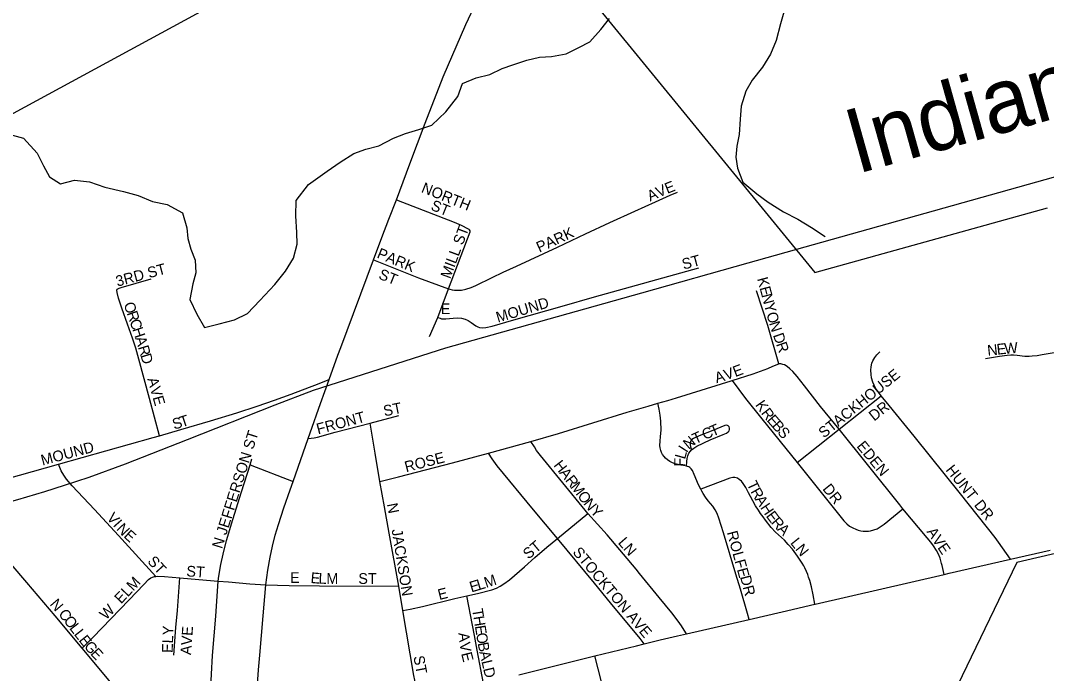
# Model space of a CAD drawing. Extents: x 1442749 to 1756758, y 235267 to 677782.
# Drawn here: x 1646641 to 1651408, y 544298 to 547333 of the extents above; entities that cross this region are included whole.
import ezdxf

# ---------------------------------------------------------------- set-up
doc = ezdxf.new("R2010")
doc.units = 0
for name, color, linetype in [('GM_X_City_Street', 7, 'Continuous'), ('GM_X_City_Street_Text', 7, 'Continuous'), ('GM_X_Corporation', 7, 'Continuous'), ('GM_X_Minor_River', 7, 'Continuous'), ('GM_X_Rail_Line', 7, 'Continuous'), ('GM_X_Rail_Line_Text', 7, 'Continuous'), ('GM_X_State_Route', 7, 'Continuous'), ('GM_X_US_Route', 7, 'Continuous')]:
    doc.layers.add(name, color=color, linetype=linetype)

msp = doc.modelspace()

# ---------------------------------------------------------------- linework, layer by layer
at = {"layer": 'GM_X_City_Street'}
for points in [[(1648629.7, 546086.1), (1648635.4, 546084.4), (1648646.7, 546082.1), (1648658, 546080.3), (1648674.3, 546079.3), (1648690.6, 546080.5), (1648709.9, 546084.4), (1648735, 546092.1), (1648756.2, 546100.9), (1648832.5, 546138.9), (1648882.9, 546162.7), (1648945.1, 546192), (1649135.5, 546280.2), (1649266.1, 546341.5), (1649379.2, 546393.9), (1649495.8, 546446.3), (1649591, 546490.4), (1649659.7, 546521.4), (1649693.3, 546534.6)], [(1648387.4, 546500.2), (1648656.3, 546396.2), (1648689.2, 546381.5), (1648721.2, 546365), (1648724, 546363.3), (1648727.5, 546359.9)], [(1648629.7, 546086.1), (1648729.7, 546351), (1648729.7, 546355.9), (1648727.5, 546359.9)], [(1648280.6, 546220.6), (1648490.8, 546137.6), (1648629.7, 546086.1)], [(1648580.4, 545953.1), (1648591.2, 545949.2), (1648597.5, 545947), (1648605.5, 545946.1), (1648618, 545947), (1648651.5, 545950.4), (1648671.2, 545951), (1648690.8, 545949.4), (1648706.7, 545945.4), (1648721.4, 545938.4), (1648735.1, 545929.3), (1648756.6, 545913.9), (1648765.2, 545909.3), (1648774.3, 545906), (1648787.2, 545904.2), (1648803.4, 545905.9), (1648832.2, 545912.9), (1648933.1, 545942), (1649157.3, 546005), (1649308.7, 546048.4), (1649792.4, 546183.4)], [(1647089.8, 546084.5), (1647100.1, 546089.4), (1647108.6, 546092.1), (1647247.7, 546132.5)], [(1647287.4, 545403.1), (1647240.7, 545576.6), (1647215.9, 545668.2), (1647190.8, 545759.7), (1647176.1, 545810.1), (1647161.8, 545856.9), (1647138.7, 545921.6), (1647112.2, 545996), (1647096.6, 546042), (1647089.8, 546069.7), (1647089, 546079.1), (1647089.8, 546084.5)], [(1648580.4, 545953.1), (1648629.7, 546086.1)], [(1650165.1, 545737.4), (1650113.2, 545915.3), (1650061.4, 546077.4)], [(1648541.5, 545864.6), (1648580.4, 545953.1)], [(1651125.6, 545761.6), (1651190.2, 545773.4), (1651225.9, 545777.9), (1651242.2, 545778.7), (1651255.5, 545778.7), (1651271.7, 545778), (1651307.5, 545773.7), (1651327.1, 545773), (1651342.1, 545774), (1651365.5, 545776.7), (1651388.9, 545780.6), (1652010, 545884.6), (1652235.6, 545927.9), (1652271, 545935.5), (1652290.3, 545939.3), (1652313.4, 545942.8), (1652329.9, 545942.9), (1652337, 545942.2)], [(1650640, 545588.9), (1650631.7, 545599.1), (1650616.5, 545620.4), (1650607.1, 545637.7), (1650600.8, 545652.8), (1650595.3, 545671.6), (1650592.9, 545687.9), (1650592.2, 545707.5), (1650593.6, 545723.8), (1650597.2, 545739.8), (1650601.9, 545752.1), (1650610.1, 545766.2), (1650620.2, 545779.1), (1650633.7, 545793.4)], [(1649947.6, 545659.3), (1650045.4, 545691.5), (1650113, 545716.4), (1650137.4, 545726.1), (1650165.1, 545737.4)], [(1650444.3, 545433.6), (1650358.5, 545539.4), (1650284.6, 545635.8), (1650249.8, 545679.3), (1650230.2, 545701.3), (1650215.9, 545714.8), (1650202.7, 545724.5), (1650190.2, 545732.4), (1650183.5, 545735.1), (1650174.5, 545737.4), (1650165.1, 545737.4)], [(1647287.4, 545403.1), (1647386.1, 545431.8), (1647524.5, 545472.7), (1647646.7, 545510.1), (1647740, 545541.3), (1647820.8, 545568.4), (1647897.8, 545596.3), (1647983.6, 545628.9), (1648008, 545638.4), (1648074.5, 545664.5)], [(1649603.1, 545554), (1649648.3, 545567.1), (1649689.1, 545579.3), (1649942.7, 545657.7), (1649947.6, 545659.3)], [(1649947.6, 545659.3), (1650009.7, 545576.8), (1650085.6, 545482.3), (1650249, 545278.8)], [(1650444.3, 545433.6), (1650640, 545588.9)], [(1651240.6, 544829.5), (1651185.5, 544908.9), (1651169.9, 544929.9), (1651008.8, 545132.6), (1650793, 545400.7), (1650677.4, 545543.3), (1650640, 545588.9)], [(1649012.3, 545377.2), (1649140.5, 545413.3), (1649459.5, 545512.3), (1649557, 545540.6), (1649603.1, 545554)], [(1649736.1, 545261.4), (1649720.9, 545264.3), (1649709.3, 545266.6), (1649696.8, 545269.3), (1649683.4, 545272.4), (1649670.7, 545277.1), (1649658, 545284.1), (1649646.8, 545291.7), (1649638.3, 545298.4), (1649631.1, 545306), (1649624, 545315.3), (1649618.6, 545325.6), (1649615.9, 545334.6), (1649613.7, 545347.1), (1649612.3, 545358.3), (1649613.5, 545377.4), (1649615, 545399.4), (1649617.7, 545429.6), (1649616.4, 545471.7), (1649613.3, 545499.2), (1649608.1, 545527), (1649603.1, 545554)], [(1648265.2, 545462.2), (1648398.7, 545497.1)], [(1647977.3, 545390), (1648005.6, 545393.8), (1648020.4, 545396.9), (1648103.1, 545419.8), (1648265.2, 545462.2)], [(1648311.1, 545191.1), (1648288.7, 545321.5), (1648265.2, 545462.2)], [(1649736.1, 545261.4), (1649737.8, 545284), (1649738.9, 545297.1), (1649741.7, 545310), (1649746.6, 545322.2), (1649751.9, 545330.5), (1649759, 545338), (1649769.5, 545345.8), (1649782.8, 545354.4), (1649845.4, 545383.6), (1649906.3, 545408.3), (1649920.9, 545415.7), (1649929.3, 545421.1), (1649933.8, 545425.8), (1649936.1, 545431.8), (1649936, 545438.4), (1649933.5, 545444.4), (1649928.9, 545449), (1649926, 545450.5), (1649919.7, 545451.8), (1649913.3, 545450.8), (1649858.5, 545428.2), (1649794.4, 545402.5), (1649767.7, 545389.8), (1649760.1, 545385.1), (1649755.7, 545379.1), (1649753, 545370.8), (1649752.5, 545362.3), (1649754.8, 545351.6), (1649759, 545338)], [(1650249, 545278.8), (1650444.3, 545433.6)], [(1650741.3, 545064), (1650726.5, 545081.8), (1650444.3, 545433.6)], [(1646817.2, 545271.3), (1647257, 545394.3), (1647287.4, 545403.1)], [(1648815.8, 545321.9), (1649012.3, 545377.2)], [(1649277.4, 545042.2), (1649264.2, 545057), (1649056.6, 545310.7), (1649038.8, 545334.1), (1649028.5, 545350.9), (1649012.3, 545377.2)], [(1647707.5, 545267.8), (1647716.2, 545295.9)], [(1648311.1, 545191.1), (1648397, 545212.3), (1648647.6, 545277.6), (1648815.8, 545321.9)], [(1649135.4, 544925.1), (1649024.6, 545058.5), (1648856.2, 545263.7), (1648833, 545295.5), (1648815.8, 545321.9)], [(1646322, 545131.4), (1646817.2, 545271.3)], [(1647270.1, 544749.5), (1647095.5, 544939), (1646984.7, 545060.2), (1646881, 545170.5), (1646855.3, 545200.8), (1646841.5, 545219.8), (1646830.4, 545240.9), (1646817.2, 545271.3)], [(1647560, 544727.6), (1647562.6, 544750.3), (1647572, 544805.1), (1647582.3, 544853.2), (1647598.5, 544916.8), (1647627.7, 545014.2), (1647668.5, 545142.4), (1647707.5, 545267.8)], [(1647707.5, 545267.8), (1647908.1, 545190.6)], [(1649802.2, 545155.3), (1649791.7, 545175.8), (1649771.1, 545223.8), (1649762.9, 545241.7), (1649757.6, 545250.1), (1649751.8, 545255.5), (1649746, 545258.6), (1649740.1, 545260.6), (1649736.1, 545261.4)], [(1650249, 545278.8), (1650467.2, 545007.2), (1650480.9, 544993.1), (1650493.6, 544982.9), (1650507.7, 544974.6), (1650522.8, 544968.3), (1650533.4, 544964.6), (1650545.5, 544961.9), (1650557.1, 544960.1), (1650568.7, 544959.2), (1650581.2, 544959.6), (1650590.4, 544960.9), (1650606.2, 544965.3), (1650621.4, 544971.3), (1650635.7, 544979.2), (1650654.4, 544992.6), (1650741.3, 545064)], [(1648398.1, 544703.7), (1648354.1, 544950.3), (1648332.5, 545073), (1648311.1, 545191.1)], [(1650332.5, 544620.3), (1650323.6, 544663.1), (1650315.7, 544701.3), (1650308.3, 544730.4), (1650303.2, 544745.4), (1650298.8, 544758.3), (1650292.9, 544772.8), (1650285.2, 544789.4), (1650280.4, 544798.7), (1650272.3, 544811), (1650263.8, 544825.1), (1650250.8, 544844.1), (1650227.5, 544875.8), (1650208.5, 544898.5), (1650190.3, 544917.3), (1650149.6, 544955.6), (1650129.6, 544977.3), (1650102.6, 545010.4), (1650091.1, 545026.2), (1650079.4, 545042.2), (1650069.8, 545057.2), (1650056.4, 545078.1), (1650043.6, 545101.1), (1650032.3, 545121.1), (1650023.2, 545138.5), (1650011, 545161.9), (1649998.9, 545181.5), (1649990.7, 545191.7), (1649981, 545200.5), (1649972.6, 545205.6), (1649966.5, 545207.8), (1649960.1, 545208.9), (1649950.3, 545208.5), (1649937.5, 545205.6), (1649802.2, 545155.3)], [(1650027.1, 544549.4), (1650019, 544577.5), (1649986.4, 544690.9), (1649965.2, 544759.9), (1649907.9, 544951.7), (1649886.4, 545020.6), (1649878, 545042), (1649868.7, 545059.2), (1649857.5, 545075.4), (1649836.4, 545100.5), (1649823.3, 545118.3), (1649812.9, 545134.3), (1649807.1, 545145.5), (1649802.2, 545155.3)], [(1650932.8, 544759), (1650923.4, 544799.6), (1650921, 544809.1), (1650913.8, 544834.3), (1650906.5, 544852.6), (1650897.1, 544869.8), (1650882.6, 544891.6), (1650870.3, 544908.7), (1650854.5, 544928), (1650741.3, 545064)], [(1649135.4, 544925.1), (1649277.4, 545042.2)], [(1649735.5, 544483), (1649717.7, 544512.1), (1649712.5, 544520.5), (1649697.3, 544541.8), (1649666.8, 544580.4), (1649608.6, 544651.2), (1649517.1, 544762.7), (1649501, 544783.1), (1649366.7, 544942.1), (1649277.4, 545042.2)], [(1646926.7, 544416.6), (1646801.7, 544566.9), (1646670.2, 544721.8), (1646513.7, 544903.1)], [(1648715.1, 544658.8), (1648764.2, 544669.8), (1648830.8, 544687.5), (1648852.4, 544695.2), (1648870.1, 544703.9), (1648886.8, 544714.2), (1648912.7, 544734.3), (1648982.3, 544794.2), (1649031.5, 544837.7), (1649086.1, 544884.9), (1649135.4, 544925.1)], [(1649539.6, 544436.1), (1649519.9, 544460.1), (1649382.5, 544627.1), (1649307.5, 544718.2), (1649135.4, 544925.1)], [(1646926.7, 544416.6), (1646976.8, 544466.2), (1647146.1, 544640.3), (1647213.7, 544711.9), (1647236.4, 544734.9), (1647246.3, 544742.3), (1647254.3, 544746.2), (1647262.9, 544748.7), (1647270.1, 544749.5)], [(1647270.1, 544749.5), (1647279.6, 544750.6), (1647310.7, 544748.7), (1647380.6, 544742.4)], [(1647353, 544383.2), (1647363.4, 544512.7), (1647369.7, 544591.5), (1647380.6, 544742.4)], [(1647380.6, 544742.4), (1647434.6, 544738), (1647560, 544727.6)], [(1647518.4, 544129.4), (1647523.5, 544207.6), (1647532.8, 544381.2), (1647547.9, 544564.2), (1647560, 544727.6)], [(1647560, 544727.6), (1647608, 544723.7), (1647706, 544715.3), (1647780.5, 544710.2)], [(1647780.5, 544710.2), (1647889, 544707.9), (1648029.7, 544706.1), (1648398.1, 544703.7)], [(1648418, 544590.5), (1648398.1, 544703.7)], [(1648418, 544590.5), (1648452.2, 544597.4), (1648508.8, 544609.4), (1648658.5, 544646.1), (1648715.1, 544658.8)], [(1648792.1, 544251.8), (1648762.5, 544407), (1648750.3, 544474.4), (1648741.6, 544522.3), (1648715.1, 544658.8)], [(1648496.2, 544178.1), (1648488.9, 544203.2), (1648477.7, 544244.8), (1648469.2, 544289), (1648418, 544590.5)], [(1647157.7, 544139.9), (1647104, 544204.3), (1646998.8, 544330), (1646926.7, 544416.6)], [(1649446.5, 543840.7), (1649373.8, 544132.7), (1649309.1, 544379.8)]]:
    msp.add_lwpolyline(points, dxfattribs=at)
at = {"layer": 'GM_X_Corporation'}
for points in [[(1648778.3, 548061.1), (1650332.2, 546161.2), (1651413, 546463.1)], [(1652114.9, 545011.1), (1651269.8, 544813.5), (1650361.2, 542928.4), (1651124.9, 542577.6), (1650104.1, 541664), (1649520.7, 542211.3), (1648766.1, 541499), (1648482, 541930.2), (1646734.2, 541962.5), (1645443.9, 543575.4), (1644770.3, 543343.8), (1644478.4, 543615.9), (1644333.9, 543780.2), (1643956.3, 544219.1), (1643887.6, 544303.8), (1644660.8, 544533), (1644252.8, 545033.8), (1646118.2, 546637.1), (1648217.2, 547777.1)]]:
    msp.add_lwpolyline(points, dxfattribs=at)
at = {"layer": 'GM_X_Minor_River'}
for points in [[(1646587.1, 546804.7), (1646655.2, 546785.8), (1646718.6, 546716.9), (1646748, 546658.4), (1646775.5, 546606), (1646827.3, 546573.3), (1646891.8, 546590.6), (1646962.1, 546583.8), (1647032.1, 546559), (1647120.2, 546537.9), (1647188.3, 546519.1), (1647254.2, 546492.3), (1647322.4, 546477.5), (1647394.2, 546438.6), (1647413.5, 546370.2), (1647418.9, 546319.9), (1647432.3, 546269.7), (1647451.8, 546219.3), (1647455.1, 546161.1), (1647442.4, 546109.1), (1647427.5, 546037), (1647460.8, 545968.5), (1647496.2, 545905.9), (1647564.7, 545923.2), (1647635.3, 545942.4), (1647695.9, 545971.8), (1647752.9, 546031.4), (1647822.1, 546106.8), (1647873, 546168.4), (1647909.9, 546228.2), (1647926.8, 546294.2), (1647925.4, 546348.3), (1647920.3, 546424.6), (1647921.2, 546496.8), (1647978.4, 546570.4), (1648065.5, 546633.6), (1648126.3, 546675), (1648189, 546714.4), (1648245.5, 546735.8), (1648306, 546751.2), (1648374.7, 546786.5), (1648429.2, 546808), (1648491.7, 546827.3), (1648552.2, 546846.7), (1648617.2, 546908.2), (1648672.3, 546979.8), (1648695.1, 547039.7), (1648757.7, 547067), (1648822.2, 547082.4), (1648878.8, 547109.8), (1648929.2, 547127.3), (1648993.8, 547148.6), (1649052.2, 547162), (1649108.5, 547165.4), (1649176.9, 547178.7), (1649235.5, 547208.1), (1649286.1, 547233.6), (1649337, 547291.2), (1649377.8, 547342.9)], [(1650187.7, 547371.8), (1650173, 547317.9), (1650151.9, 547239.9), (1650125.1, 547176), (1650088.2, 547116.2), (1650041.2, 547056.6), (1650010.5, 547004.8), (1649989.6, 546934.8), (1649984.8, 546874.7), (1649979.9, 546802.6), (1649969.2, 546748.5), (1649964.6, 546698.4), (1649972, 546646.2), (1649997.3, 546581.7), (1650063, 546526.8), (1650114.7, 546488.2), (1650186.5, 546443.2), (1650252.4, 546410.4), (1650316.2, 546371.6), (1650380, 546328.7)]]:
    msp.add_lwpolyline(points, dxfattribs=at)
at = {"layer": 'GM_X_Rail_Line'}
for points in [[(1648002.1, 545614.9), (1648617.4, 545811.2), (1649528.4, 546067.5), (1650021.6, 546206.3), (1652489.5, 546898.6), (1654040.9, 547332.8), (1657745.4, 548373), (1661321.1, 549378.1), (1663701.4, 550047.2)], [(1647824.1, 545546.7), (1648002.1, 545614.9)], [(1622992.7, 538441.5), (1624973.8, 539013.5), (1626935.6, 539566.6), (1628793.5, 540088.9), (1634516, 541702.1), (1636441.8, 542242.9), (1638391.8, 542790.8), (1640631.9, 543421.9), (1643762.7, 544302.3), (1646454, 545058.4), (1646629.2, 545107.3), (1646753.5, 545144.7), (1646845.5, 545173.3), (1646960.4, 545211.3), (1647129.3, 545272.7), (1647416.4, 545385.5), (1647824.1, 545546.7)]]:
    msp.add_lwpolyline(points, dxfattribs=at)
at = {"layer": 'GM_X_State_Route'}
for points in [[(1648129.3, 545813.6), (1648280.6, 546220.6), (1648320.1, 546324.4), (1648352.2, 546410.4), (1648387.4, 546500.2), (1648450.4, 546666.3), (1648521.3, 546856.6), (1648604.3, 547070.6), (1648709.6, 547314.2), (1648797.3, 547501.2), (1648851.2, 547613.6), (1648881.1, 547675.5), (1648907, 547724.4), (1648918.5, 547743.5), (1648932.2, 547761.9), (1648941.9, 547775.5), (1648985.8, 547825.4)], [(1647735.6, 544162.2), (1647747.4, 544314.8), (1647753.7, 544383.3), (1647768.6, 544566.5), (1647780.5, 544710.2), (1647789.9, 544778), (1647800.3, 544839.3), (1647811.3, 544890.3), (1647824.4, 544940.8), (1647839.6, 544990.3), (1647864.7, 545068.1), (1647894, 545151.3), (1647908.1, 545190.6), (1647977.3, 545390), (1647986.8, 545417.4), (1648035.5, 545553.3), (1648074.5, 545664.5), (1648116.1, 545778), (1648129.3, 545813.6)]]:
    msp.add_lwpolyline(points, dxfattribs=at)
at = {"layer": 'GM_X_US_Route'}
for points in [[(1649503.8, 544427.3), (1649539.6, 544436.1), (1649613.7, 544454), (1649693.4, 544473.4), (1649735.5, 544483), (1650027.1, 544549.4), (1650179.6, 544584.2), (1650332.5, 544620.3), (1650332.9, 544620.4), (1650932.8, 544759), (1650956.1, 544764.4), (1651240.6, 544829.5), (1651425.5, 544871.8)], [(1648956.6, 544292.6), (1649309.1, 544379.8), (1649503.8, 544427.3)]]:
    msp.add_lwpolyline(points, dxfattribs=at)

# ---------------------------------------------------------------- texts
at = {"layer": 'GM_X_City_Street_Text'}
for s, rotation, p in [('NORTH', 338.1919, (1648499.6, 546536.4)), ('V', 23.9447, (1649606.5, 546509.3)), ('E', 21.5985, (1649646.2, 546527)), ('A', 24.1799, (1649566.4, 546491.3)), ('ST', 338.2086, (1648543.5, 546454.7)), ('MILL ST', 69.5643, (1648637.4, 546129.6)), ('PARK', 24.5675, (1649051.8, 546253.8)), ('PARK', 337.6202, (1648293.4, 546231.8)), ('ST', 14.9514, (1649721.8, 546175)), ('3RD ST', 14.9326, (1647091, 546095.9)), ('ST', 338.2086, (1648301, 546134.4)), ('K', 284.8737, (1650063.3, 546133.1)), ('E', 284.888, (1650074.6, 546090.6)), ('MOUND', 16.6988, (1648859.1, 545928.5)), ('N', 284.8737, (1650083.7, 546056.6)), ('O', 288.8981, (1647119.5, 546015)), ('E', 0, (1648593.4, 545968.5)), ('Y', 284.8737, (1650095, 546014)), ('R', 288.9187, (1647133.8, 545973.3)), ('O', 285.1302, (1650106.3, 545971.2)), ('C', 288.9187, (1647146.6, 545935.9)), ('H', 288.4626, (1647159.4, 545898.5)), ('N', 287.8075, (1650118.5, 545926.3)), ('A', 287.0175, (1647173.3, 545857.1)), ('D', 289.0184, (1650136.6, 545870.9)), ('R', 286.6992, (1647186.1, 545815.1)), ('R', 289.0385, (1650151, 545829.3)), ('N', 6.176, (1651135.6, 545774.8)), ('E', 6.132, (1651179.3, 545779.6)), ('W', 4.7804, (1651214, 545783.3)), ('D', 286.6867, (1647197.5, 545777.2)), ('V', 18.826, (1649918.7, 545660.5)), ('E', 20.8842, (1649962.2, 545675.3)), ('STACKHOUSE', 38.8504, (1650374, 545390.1)), ('AVE', 285.9444, (1647229.7, 545666.9)), ('A', 17.4049, (1649875.4, 545646.9)), ('K', 304.8237, (1650053.2, 545546.5)), ('ST', 11.3323, (1648332, 545493.1)), ('R', 307.4647, (1650079.8, 545508.3)), ('DR', 38.6634, (1650607.5, 545468.8)), ('S', 16.5082, (1647354.6, 545431.4)), ('T', 18.1877, (1647389.9, 545441.9)), ('FRONT', 14.932, (1648023.4, 545409.4)), ('E', 310.8607, (1650105.9, 545474.4)), ('B', 311.0183, (1650129.1, 545447.6)), ('N JEFFERSON ST', 72.5532, (1647576.9, 544875.1)), ('T', 24.5118, (1649776.3, 545363.4)), ('C', 23.1093, (1649820.1, 545383.1)), ('T', 23.0192, (1649856.5, 545398.7)), ('S', 311.0163, (1650155, 545417.8)), ('N', 40.0798, (1649745.6, 545337)), ('EDEN', 309.6093, (1650523.5, 545353.5)), ('MOUND', 14.9301, (1646743, 545264.3)), ('I', 57.207, (1649736.3, 545321.4)), ('ROSE', 14.425, (1648432.7, 545233.4)), ('H', 307.8405, (1649115.7, 545265.3)), ('F', 88.6608, (1649728, 545259.2)), ('L', 74.201, (1649728.4, 545291.1)), ('A', 307.8405, (1649142.7, 545230.6)), ('HUNT', 308.6634, (1650937.2, 545243.4)), ('R', 307.8218, (1649169.7, 545195.8)), ('M', 307.8318, (1649193.9, 545164.5)), ('T', 295.3436, (1650014.4, 545179.4)), ('O', 307.8254, (1649226.3, 545122.8)), ('R', 299.6456, (1650031.4, 545143.9)), ('DR', 308.6634, (1650365.2, 545155.4)), ('N', 308.6426, (1649253.8, 545087.5)), ('A', 302.1312, (1650052.2, 545107.5)), ('H', 303.7957, (1650076.4, 545068.9)), ('DR', 308.6545, (1651069.2, 545080.6)), ('V', 311.5355, (1647038.5, 545019.3)), ('N', 281.3225, (1648343, 545085.4)), ('Y', 313.8527, (1649284.6, 545049.4)), ('E', 306.7504, (1650102.5, 545030)), ('I', 311.5065, (1647067.7, 544986.4)), ('N', 313.7443, (1647083.7, 544968.4)), ('R', 310.8679, (1650126, 544998.8)), ('E', 318.028, (1647117, 544933.8)), ('JACKSON', 279.1602, (1648365.1, 544966.2)), ('ROLFE', 285.2543, (1649922.5, 544954)), ('A', 314.4577, (1650154.3, 544966.3)), ('AVE', 304.2105, (1650849.6, 544956.9)), ('ST', 39.8092, (1649001, 544826.7)), ('LN', 310.9166, (1649414.5, 544904.9)), ('LN', 308.6687, (1650215.4, 544904.5)), ('STOCKTON AVE', 310.0133, (1649203.7, 544860.4)), ('ST', 312.5022, (1647227.6, 544817.1)), ('ST', 356.4254, (1647410.4, 544749.7)), ('E', 0, (1647893.8, 544718.9)), ('E', 355.2954, (1647987.4, 544718.9)), ('L', 358.0586, (1648025.1, 544715.8)), ('M', 359.938, (1648062, 544714.6)), ('ST', 0, (1648210.6, 544714.6)), ('M', 18.2568, (1648804.5, 544695.4)), ('ELM', 46.4016, (1647108.2, 544619.2)), ('E', 16.9139, (1648736, 544674.5)), ('L', 16.9695, (1648769.7, 544684.8)), ('DR', 284.7487, (1649984.1, 544747.1)), ('E', 14.0298, (1648586.8, 544639.4)), ('N', 310.6193, (1646774.6, 544618.9)), ('W', 44.9879, (1647038, 544544.6)), ('C', 307.696, (1646814.5, 544574.5)), ('T', 279.2737, (1648739.1, 544596.6)), ('O', 307.6828, (1646838.7, 544543.1)), ('L', 307.6948, (1646865.6, 544508.3)), ('ELY', 87.8801, (1647347.7, 544393.1)), ('H', 279.2705, (1648744.8, 544561.9)), ('E', 279.2737, (1648751.9, 544518.5)), ('L', 307.7121, (1646887.1, 544480.5)), ('E', 308.4166, (1646909.1, 544452.1)), ('AVE', 86.0494, (1647433.5, 544383)), ('A', 275.8672, (1648675.6, 544486.3)), ('O', 279.2612, (1648757.6, 544483.7)), ('G', 311.8625, (1646933.1, 544422)), ('V', 278.1226, (1648680.4, 544440.4)), ('B', 280.3951, (1648764.9, 544439.2)), ('E', 312.8936, (1646963.1, 544388.5)), ('ST', 280.6279, (1648466.3, 544376.8)), ('E', 284.5196, (1648687.8, 544390.8)), ('A', 282.8628, (1648772.5, 544398)), ('L', 283.2376, (1648782.3, 544354.7)), ('D', 283.2479, (1648790.4, 544320.4))]:
    msp.add_text(s, height=50, rotation=rotation, dxfattribs=at).set_placement(p)
at = {"layer": 'GM_X_Rail_Line_Text'}
msp.add_text('Indiana', height=299, rotation=15.6615, dxfattribs=at).set_placement((1650526.4, 546619))

doc.saveas('drawing.dxf')
